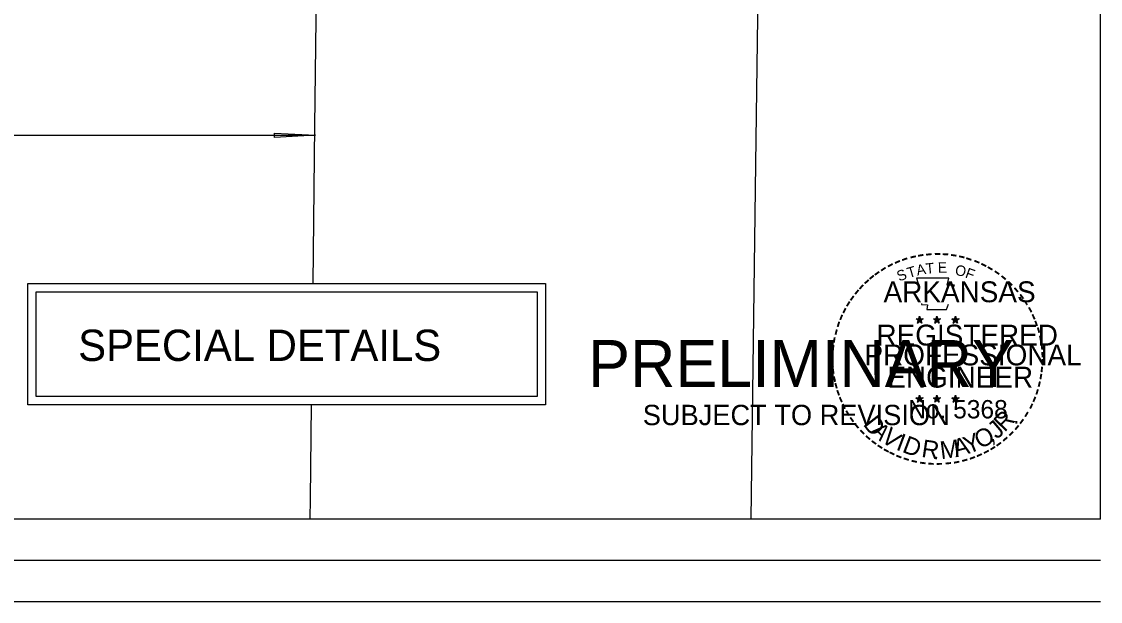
# Model space of a CAD drawing. Extents: x 1944905 to 1956777, y 763871 to 764977.
# Drawn here: x 1949424 to 1949941, y 763871 to 764148 of the extents above; entities that cross this region are included whole.
import ezdxf

# ---------------------------------------------------------------- set-up
doc = ezdxf.new("R2010")
doc.units = 0
for name, color, linetype in [('Default', 7, 'Continuous'), ('R_Border PE', 7, 'Continuous'), ('S_EDGE_PAVEMENT', 7, 'Continuous')]:
    doc.layers.add(name, color=color, linetype=linetype)

msp = doc.modelspace()

# ---------------------------------------------------------------- linework, layer by layer
at = {"layer": 'Default'}
for p, q in [((1949941.01, 763910.07), (1949941.01, 764937.29)), ((1949545.33, 764094.92), (1949545.4, 764094.92)), ((1949545.4, 764094.92), (1949564.95, 764093.95)), ((1949545.4, 764092.97), (1949545.4, 764094.92)), ((1949364.95, 764093.95), (1949564.95, 764093.95)), ((1949564.95, 764093.95), (1949545.4, 764092.97)), ((1949941.01, 763910.07), (1948360.11, 763910.07)), ((1948327.27, 763890.36), (1949941.01, 763890.36)), ((1948327.27, 763870.67), (1949941.01, 763870.67))]:
    msp.add_line(p, q, dxfattribs=at)
for points in [[(1949427.11, 764022.9), (1949675.12, 764022.9), (1949675.12, 763964.87), (1949427.11, 763964.87)], [(1949431.11, 764018.9), (1949671.12, 764018.9), (1949671.12, 763968.87), (1949431.11, 763968.87)]]:
    msp.add_lwpolyline(points, close=True, dxfattribs=at)
at = {"layer": 'R_Border PE'}
for p, q in [((1949854.37, 764007.29), (1949854.12, 764006.09)), ((1949854.37, 764007.29), (1949854.17, 764006.04)), ((1949854.37, 764007.29), (1949854.32, 764006.04)), ((1949854.37, 764005.49), (1949854.37, 764007.29)), ((1949854.37, 764007.29), (1949854.72, 764006.04)), ((1949854.37, 764007.29), (1949854.62, 764006.04)), ((1949854.37, 764007.29), (1949854.52, 764006.09)), ((1949862.72, 764007.29), (1949862.47, 764006.09)), ((1949862.72, 764007.29), (1949862.52, 764006.04)), ((1949862.72, 764007.29), (1949862.67, 764006.04)), ((1949862.72, 764005.49), (1949862.72, 764007.29)), ((1949862.72, 764007.29), (1949863.07, 764006.04)), ((1949862.72, 764007.29), (1949862.97, 764006.04)), ((1949862.72, 764007.29), (1949862.87, 764006.09)), ((1949871.57, 764007.24), (1949871.27, 764006.04)), ((1949871.57, 764007.24), (1949871.37, 764005.99)), ((1949871.57, 764007.24), (1949871.47, 764005.99)), ((1949871.57, 764005.44), (1949871.57, 764007.24)), ((1949871.57, 764007.24), (1949871.92, 764005.99)), ((1949871.57, 764007.24), (1949871.82, 764005.99)), ((1949871.57, 764007.24), (1949871.67, 764006.04)), ((1949852.67, 764006.04), (1949854.37, 764005.49)), ((1949852.67, 764006.04), (1949853.92, 764005.89)), ((1949852.67, 764006.04), (1949853.92, 764005.84)), ((1949852.67, 764006.04), (1949853.87, 764005.74)), ((1949852.67, 764006.04), (1949853.87, 764005.54)), ((1949852.67, 764006.04), (1949853.82, 764005.44)), ((1949852.67, 764006.04), (1949853.82, 764005.34)), ((1949853.32, 764003.99), (1949854.37, 764005.49)), ((1949853.32, 764003.99), (1949853.87, 764005.39)), ((1949853.32, 764003.99), (1949853.92, 764005.24)), ((1949853.32, 764003.99), (1949854.02, 764005.19)), ((1949853.32, 764003.99), (1949854.37, 764005.09)), ((1949853.32, 764003.99), (1949854.17, 764005.04)), ((1949853.32, 764003.99), (1949854.42, 764004.94)), ((1949856.12, 764006.04), (1949854.37, 764005.49)), ((1949855.47, 764003.99), (1949854.37, 764005.49)), ((1949855.47, 764003.99), (1949854.37, 764005.09)), ((1949855.47, 764003.99), (1949854.37, 764004.94)), ((1949855.47, 764003.99), (1949854.57, 764005.04)), ((1949856.12, 764006.04), (1949854.62, 764005.94)), ((1949856.12, 764006.04), (1949854.72, 764005.79)), ((1949856.12, 764006.04), (1949854.72, 764005.69)), ((1949855.47, 764003.99), (1949854.72, 764005.24)), ((1949855.47, 764003.99), (1949854.77, 764005.44)), ((1949855.47, 764003.99), (1949854.87, 764005.44)), ((1949856.12, 764006.04), (1949855.02, 764005.59)), ((1949856.12, 764006.04), (1949855.12, 764005.54)), ((1949856.12, 764006.04), (1949855.17, 764005.49)), ((1949860.97, 764006.04), (1949862.72, 764005.49)), ((1949860.97, 764006.04), (1949862.27, 764005.89)), ((1949860.97, 764006.04), (1949862.27, 764005.84)), ((1949860.97, 764006.04), (1949862.22, 764005.74)), ((1949860.97, 764006.04), (1949862.22, 764005.54)), ((1949860.97, 764006.04), (1949862.17, 764005.44)), ((1949860.97, 764006.04), (1949862.17, 764005.34)), ((1949861.67, 764003.99), (1949862.72, 764005.49)), ((1949861.67, 764003.99), (1949862.22, 764005.39)), ((1949861.67, 764003.99), (1949862.27, 764005.24)), ((1949861.67, 764003.99), (1949862.37, 764005.19)), ((1949861.67, 764003.99), (1949862.72, 764005.09)), ((1949861.67, 764003.99), (1949862.52, 764005.04)), ((1949861.67, 764003.99), (1949862.77, 764004.94)), ((1949864.47, 764006.04), (1949862.72, 764005.49)), ((1949863.82, 764003.99), (1949862.72, 764005.49)), ((1949863.82, 764003.99), (1949862.72, 764005.09)), ((1949863.82, 764003.99), (1949862.72, 764004.94)), ((1949864.47, 764006.04), (1949862.92, 764005.94)), ((1949863.82, 764003.99), (1949862.92, 764005.04)), ((1949864.47, 764006.04), (1949863.02, 764005.79)), ((1949864.47, 764006.04), (1949863.02, 764005.69)), ((1949863.82, 764003.99), (1949863.07, 764005.24)), ((1949863.82, 764003.99), (1949863.12, 764005.44)), ((1949863.82, 764003.99), (1949863.22, 764005.44)), ((1949864.47, 764006.04), (1949863.37, 764005.59)), ((1949864.47, 764006.04), (1949863.47, 764005.54)), ((1949864.47, 764006.04), (1949863.52, 764005.49)), ((1949869.82, 764005.99), (1949871.57, 764005.44)), ((1949869.82, 764005.99), (1949871.12, 764005.84)), ((1949869.82, 764005.99), (1949871.12, 764005.74)), ((1949869.82, 764005.99), (1949871.07, 764005.64)), ((1949869.82, 764005.99), (1949871.02, 764005.49)), ((1949869.82, 764005.99), (1949871.02, 764005.39)), ((1949869.82, 764005.99), (1949871.02, 764005.29)), ((1949870.52, 764003.94), (1949871.57, 764005.44)), ((1949870.52, 764003.94), (1949871.07, 764005.34)), ((1949870.52, 764003.94), (1949871.12, 764005.14)), ((1949870.52, 764003.94), (1949871.22, 764005.14)), ((1949870.52, 764003.94), (1949871.57, 764005.04)), ((1949870.52, 764003.94), (1949871.37, 764004.99)), ((1949870.52, 764003.94), (1949871.62, 764004.89)), ((1949873.32, 764005.99), (1949871.57, 764005.44)), ((1949872.62, 764003.94), (1949871.57, 764005.44)), ((1949872.62, 764003.94), (1949871.57, 764005.04)), ((1949872.62, 764003.94), (1949871.57, 764004.89)), ((1949873.32, 764005.99), (1949871.77, 764005.89)), ((1949872.62, 764003.94), (1949871.77, 764004.99)), ((1949873.32, 764005.99), (1949871.87, 764005.74)), ((1949873.32, 764005.99), (1949871.87, 764005.64)), ((1949872.62, 764003.94), (1949871.92, 764005.19)), ((1949872.62, 764003.94), (1949871.97, 764005.39)), ((1949872.62, 764003.94), (1949872.07, 764005.39)), ((1949873.32, 764005.99), (1949872.22, 764005.54)), ((1949873.32, 764005.99), (1949872.27, 764005.49)), ((1949873.32, 764005.99), (1949872.37, 764005.44)), ((1949852.62, 763968.19), (1949854.37, 763967.64)), ((1949852.62, 763968.19), (1949853.92, 763968.04)), ((1949852.62, 763968.19), (1949853.92, 763967.94)), ((1949852.62, 763968.19), (1949853.87, 763967.84)), ((1949852.62, 763968.19), (1949853.82, 763967.69)), ((1949852.62, 763968.19), (1949853.82, 763967.59)), ((1949852.62, 763968.19), (1949853.82, 763967.44)), ((1949853.32, 763966.14), (1949854.37, 763967.64)), ((1949853.32, 763966.14), (1949853.87, 763967.54)), ((1949853.32, 763966.14), (1949853.92, 763967.34)), ((1949853.32, 763966.14), (1949854.02, 763967.29)), ((1949853.32, 763966.14), (1949854.37, 763967.24)), ((1949853.32, 763966.14), (1949854.17, 763967.19)), ((1949853.32, 763966.14), (1949854.42, 763967.09)), ((1949854.37, 763969.44), (1949854.07, 763968.24)), ((1949854.37, 763969.44), (1949854.17, 763968.19)), ((1949854.37, 763969.44), (1949854.27, 763968.19)), ((1949854.37, 763967.64), (1949854.37, 763969.44)), ((1949854.37, 763969.44), (1949854.72, 763968.19)), ((1949854.37, 763969.44), (1949854.62, 763968.19)), ((1949854.37, 763969.44), (1949854.47, 763968.19)), ((1949856.12, 763968.19), (1949854.37, 763967.64)), ((1949855.42, 763966.14), (1949854.37, 763967.64)), ((1949855.42, 763966.14), (1949854.37, 763967.19)), ((1949855.42, 763966.14), (1949854.37, 763967.09)), ((1949856.12, 763968.19), (1949854.57, 763968.09)), ((1949855.42, 763966.14), (1949854.57, 763967.19)), ((1949856.12, 763968.19), (1949854.67, 763967.94)), ((1949856.12, 763968.19), (1949854.67, 763967.84)), ((1949855.42, 763966.14), (1949854.72, 763967.34)), ((1949855.42, 763966.14), (1949854.77, 763967.59)), ((1949855.42, 763966.14), (1949854.87, 763967.59)), ((1949856.12, 763968.19), (1949855.02, 763967.74)), ((1949856.12, 763968.19), (1949855.07, 763967.69)), ((1949856.12, 763968.19), (1949855.17, 763967.59)), ((1949860.97, 763968.19), (1949862.72, 763967.64)), ((1949860.97, 763968.19), (1949862.27, 763968.04)), ((1949860.97, 763968.19), (1949862.22, 763967.94)), ((1949860.97, 763968.19), (1949862.22, 763967.84)), ((1949860.97, 763968.19), (1949862.17, 763967.69)), ((1949860.97, 763968.19), (1949862.17, 763967.59)), ((1949860.97, 763968.19), (1949862.17, 763967.44)), ((1949861.62, 763966.14), (1949862.72, 763967.64)), ((1949861.62, 763966.14), (1949862.22, 763967.54)), ((1949861.62, 763966.14), (1949862.27, 763967.34)), ((1949861.62, 763966.14), (1949862.37, 763967.29)), ((1949861.62, 763966.14), (1949862.72, 763967.24)), ((1949861.62, 763966.14), (1949862.52, 763967.19)), ((1949861.62, 763966.14), (1949862.72, 763967.09)), ((1949862.72, 763969.44), (1949862.42, 763968.24)), ((1949862.72, 763969.44), (1949862.52, 763968.19)), ((1949862.72, 763969.44), (1949862.62, 763968.19)), ((1949862.72, 763967.64), (1949862.72, 763969.44)), ((1949862.72, 763969.44), (1949863.07, 763968.19)), ((1949862.72, 763969.44), (1949862.97, 763968.19)), ((1949862.72, 763969.44), (1949862.82, 763968.19)), ((1949864.47, 763968.19), (1949862.72, 763967.64)), ((1949863.77, 763966.14), (1949862.72, 763967.64)), ((1949863.77, 763966.14), (1949862.72, 763967.19)), ((1949863.77, 763966.14), (1949862.72, 763967.09)), ((1949864.47, 763968.19), (1949862.92, 763968.09)), ((1949863.77, 763966.14), (1949862.92, 763967.19)), ((1949864.47, 763968.19), (1949863.02, 763967.94)), ((1949864.47, 763968.19), (1949863.02, 763967.84)), ((1949863.77, 763966.14), (1949863.07, 763967.34)), ((1949863.77, 763966.14), (1949863.12, 763967.59)), ((1949863.77, 763966.14), (1949863.22, 763967.59)), ((1949864.47, 763968.19), (1949863.32, 763967.74)), ((1949864.47, 763968.19), (1949863.42, 763967.69)), ((1949864.47, 763968.19), (1949863.52, 763967.59)), ((1949869.82, 763968.14), (1949871.57, 763967.54)), ((1949869.82, 763968.14), (1949871.07, 763967.99)), ((1949869.82, 763968.14), (1949871.07, 763967.89)), ((1949869.82, 763968.14), (1949871.02, 763967.79)), ((1949869.82, 763968.14), (1949871.02, 763967.64)), ((1949869.82, 763968.14), (1949870.97, 763967.49)), ((1949869.82, 763968.14), (1949870.97, 763967.39)), ((1949870.47, 763966.09), (1949871.57, 763967.54)), ((1949870.47, 763966.09), (1949871.02, 763967.44)), ((1949870.47, 763966.09), (1949871.12, 763967.29)), ((1949870.47, 763966.09), (1949871.22, 763967.24)), ((1949870.47, 763966.09), (1949871.37, 763967.14)), ((1949870.47, 763966.09), (1949871.52, 763967.14)), ((1949870.47, 763966.09), (1949871.57, 763967.04)), ((1949871.57, 763969.39), (1949871.27, 763968.14)), ((1949871.57, 763969.39), (1949871.37, 763968.14)), ((1949871.57, 763969.39), (1949871.47, 763968.14)), ((1949872.62, 763966.09), (1949871.52, 763967.14)), ((1949872.62, 763966.09), (1949871.52, 763966.99)), ((1949871.57, 763967.54), (1949871.57, 763969.39)), ((1949871.57, 763969.39), (1949871.87, 763968.14)), ((1949871.57, 763969.39), (1949871.82, 763968.14)), ((1949871.57, 763969.39), (1949871.67, 763968.14)), ((1949873.27, 763968.14), (1949871.57, 763967.54)), ((1949872.62, 763966.09), (1949871.57, 763967.54)), ((1949872.62, 763966.09), (1949871.72, 763967.14)), ((1949873.27, 763968.14), (1949871.77, 763967.99)), ((1949873.27, 763968.14), (1949871.87, 763967.89)), ((1949873.27, 763968.14), (1949871.87, 763967.79)), ((1949872.62, 763966.09), (1949871.92, 763967.54)), ((1949872.62, 763966.09), (1949871.92, 763967.29)), ((1949872.62, 763966.09), (1949872.07, 763967.54)), ((1949873.27, 763968.14), (1949872.17, 763967.64)), ((1949873.27, 763968.14), (1949872.27, 763967.59)), ((1949873.27, 763968.14), (1949872.32, 763967.54))]:
    msp.add_line(p, q, dxfattribs=at)
for points in [[(1949852.87, 764025.44), (1949854.22, 764021.29)], [(1949870.42, 764020.84), (1949871.12, 764022.24), (1949867.67, 764022.14), (1949868.42, 764025.44), (1949852.87, 764025.44)], [(1949855.32, 764013.34), (1949855.32, 764012.89), (1949858.12, 764012.79), (1949857.87, 764010.44), (1949867.22, 764010.44), (1949868.22, 764013.09)], [(1949854.37, 764007.29), (1949855.47, 764003.99), (1949852.67, 764006.04), (1949856.12, 764006.04), (1949853.32, 764003.99), (1949854.37, 764007.29)], [(1949862.72, 764007.29), (1949863.82, 764003.99), (1949860.97, 764006.04), (1949864.47, 764006.04), (1949861.67, 764003.99), (1949862.72, 764007.29)], [(1949871.57, 764007.24), (1949872.62, 764003.94), (1949869.82, 764005.99), (1949873.32, 764005.99), (1949870.52, 764003.94), (1949871.57, 764007.24)], [(1949854.37, 763969.44), (1949855.42, 763966.14), (1949852.62, 763968.19), (1949856.12, 763968.19), (1949853.32, 763966.14), (1949854.37, 763969.44)], [(1949862.72, 763969.44), (1949863.77, 763966.14), (1949860.97, 763968.19), (1949864.47, 763968.19), (1949861.62, 763966.14), (1949862.72, 763969.44)], [(1949871.57, 763969.39), (1949872.62, 763966.09), (1949869.82, 763968.14), (1949873.27, 763968.14), (1949870.47, 763966.09), (1949871.57, 763969.39)]]:
    msp.add_lwpolyline(points, dxfattribs=at)
for centre, radius in [((1949854.37, 764005.49), 0.861), ((1949854.37, 764005.49), 0.78), ((1949854.37, 764005.49), 0.723), ((1949854.37, 764005.49), 0.664), ((1949854.37, 764005.49), 0.579), ((1949854.37, 764005.49), 0.537), ((1949854.37, 764005.49), 0.495), ((1949854.37, 764005.49), 0.426), ((1949854.37, 764005.49), 0.374), ((1949854.37, 764005.49), 0.311), ((1949854.37, 764005.49), 0.248), ((1949854.37, 764005.49), 0.185), ((1949854.37, 764005.49), 0.148), ((1949854.37, 764005.49), 0.0721), ((1949862.72, 764005.49), 0.861), ((1949862.72, 764005.49), 0.78), ((1949862.72, 764005.49), 0.723), ((1949862.72, 764005.49), 0.664), ((1949862.72, 764005.49), 0.579), ((1949862.72, 764005.49), 0.537), ((1949862.72, 764005.49), 0.495), ((1949862.72, 764005.49), 0.426), ((1949862.72, 764005.49), 0.374), ((1949862.72, 764005.49), 0.311), ((1949862.72, 764005.49), 0.248), ((1949862.72, 764005.49), 0.185), ((1949862.72, 764005.49), 0.148), ((1949862.72, 764005.49), 0.0721), ((1949871.56, 764005.43), 0.861), ((1949871.56, 764005.43), 0.78), ((1949871.56, 764005.43), 0.723), ((1949871.56, 764005.43), 0.664), ((1949871.56, 764005.43), 0.579), ((1949871.56, 764005.43), 0.537), ((1949871.56, 764005.43), 0.495), ((1949871.56, 764005.43), 0.426), ((1949871.56, 764005.43), 0.374), ((1949871.56, 764005.43), 0.311), ((1949871.56, 764005.43), 0.248), ((1949871.56, 764005.43), 0.185), ((1949871.56, 764005.43), 0.148), ((1949871.56, 764005.43), 0.0721), ((1949854.35, 763967.63), 0.861), ((1949854.35, 763967.63), 0.78), ((1949854.35, 763967.63), 0.723), ((1949854.35, 763967.63), 0.664), ((1949854.35, 763967.63), 0.579), ((1949854.35, 763967.63), 0.537), ((1949854.35, 763967.63), 0.495), ((1949854.35, 763967.63), 0.426), ((1949854.35, 763967.63), 0.374), ((1949854.35, 763967.63), 0.311), ((1949854.35, 763967.63), 0.248), ((1949854.35, 763967.63), 0.185), ((1949854.35, 763967.63), 0.148), ((1949854.35, 763967.63), 0.0721), ((1949862.7, 763967.63), 0.861), ((1949862.7, 763967.63), 0.78), ((1949862.7, 763967.63), 0.723), ((1949862.7, 763967.63), 0.664), ((1949862.7, 763967.63), 0.579), ((1949862.7, 763967.63), 0.537), ((1949862.7, 763967.63), 0.495), ((1949862.7, 763967.63), 0.426), ((1949862.7, 763967.63), 0.374), ((1949862.7, 763967.63), 0.311), ((1949862.7, 763967.63), 0.248), ((1949862.7, 763967.63), 0.185), ((1949862.7, 763967.63), 0.148), ((1949862.7, 763967.63), 0.0721), ((1949871.54, 763967.57), 0.861), ((1949871.54, 763967.57), 0.78), ((1949871.54, 763967.57), 0.723), ((1949871.54, 763967.57), 0.664), ((1949871.54, 763967.57), 0.579), ((1949871.54, 763967.57), 0.537), ((1949871.54, 763967.57), 0.495), ((1949871.54, 763967.57), 0.426), ((1949871.54, 763967.57), 0.374), ((1949871.54, 763967.57), 0.311), ((1949871.54, 763967.57), 0.248), ((1949871.54, 763967.57), 0.185), ((1949871.54, 763967.57), 0.148), ((1949871.54, 763967.57), 0.0721)]:
    msp.add_circle(centre, radius, dxfattribs=at)
at = {"layer": 'S_EDGE_PAVEMENT'}
for points in [[(1949563.8, 764022.9), (1949564.74, 764098.49), (1949566.96, 764276.97), (1949568.19, 764402.15), (1949569.42, 764527.32), (1949570.65, 764652.49), (1949571.88, 764777.67), (1949573.46, 764887.95)], [(1949773.62, 763910.07), (1949775.95, 764080.27), (1949778.51, 764267.61), (1949779.53, 764399.29), (1949780.54, 764530.97), (1949779.91, 764702.99), (1949781.3, 764840.56), (1949781.63, 764873.29)], [(1949562.4, 763910.07), (1949562.52, 763920.01), (1949563.08, 763964.87)]]:
    msp.add_lwpolyline(points, dxfattribs=at)

# ---------------------------------------------------------------- texts
at = {"layer": 'Default'}
for s, height, p in [('SPECIAL DETAILS', 15, (1949451.29, 763985.86)), ('PRELIMINARY', 22.5, (1949695.6, 763973.37)), ('        SUBJECT TO REVISION', 9.75, (1949692.78, 763955.1))]:
    msp.add_text(s, height=height, dxfattribs=at).set_placement(p)
at = {"layer": 'R_Border PE'}
for s, height, rotation, p in [('-', 8, 28.7918, (1949840.27, 764028.14)), ('-', 8, 24.3072, (1949843.42, 764029.74)), ('-', 8, 19.1761, (1949846.57, 764031.09)), ('-', 8, 13.6301, (1949850.32, 764032.29)), ('-', 8, 10.2193, (1949853.72, 764033.09)), ('T', 5, 6.0228, (1949857.57, 764027.54)), ('-', 8, 5.8968, (1949857.37, 764033.64)), ('-', 8, 0.1862, (1949861.22, 764033.99)), ('E', 5, 0.8323, (1949863.12, 764028.09)), ('-', 8, 357.743, (1949864.87, 764033.94)), ('-', 8, 352.1617, (1949868.57, 764033.64)), ('-', 8, 347.2049, (1949872.17, 764033.09)), ('-', 8, 342.3362, (1949875.32, 764032.29)), ('-', 8, 337.8551, (1949879.02, 764031.19)), ('-', 8, 334.1211, (1949882.17, 764029.84)), ('-', 8, 36.2317, (1949834.37, 764024.29)), ('-', 8, 34.0636, (1949837.27, 764026.29)), ('S', 5, 21.594, (1949844.62, 764023.84)), ('T', 5, 16.4036, (1949849.22, 764025.49)), ('A', 5, 11.2132, (1949853.32, 764026.74)), ('O', 5, 350.4515, (1949871.12, 764027.04)), ('F', 5, 340.0707, (1949875.87, 764025.94)), ('-', 8, 329.6409, (1949885.07, 764028.44)), ('-', 8, 325.8627, (1949888.27, 764026.59)), ('-', 8, 48.4231, (1949827.62, 764017.94)), ('-', 8, 42.9622, (1949829.82, 764020.34)), ('-', 8, 38.9507, (1949832.02, 764022.44)), ('-', 8, 320.5297, (1949891.32, 764024.49)), ('-', 8, 315.5786, (1949894.32, 764022.04)), ('-', 8, 54.2325, (1949823.52, 764012.69)), ('-', 8, 50.6142, (1949825.57, 764015.54)), ('-', 8, 309.8797, (1949897.17, 764019.29)), ('-', 8, 306.6522, (1949899.82, 764016.29)), ('-', 8, 58.0706, (1949821.87, 764010.04)), ('-', 7, 303.6753, (1949902.22, 764013.44)), ('-', 8, 67.7743, (1949819.02, 764003.94)), ('-', 8, 62.8713, (1949820.32, 764006.99)), ('-', 8, 299.6684, (1949903.82, 764010.39)), ('-', 8, 294.6628, (1949905.42, 764007.34)), ('-', 8, 72.3945, (1949817.92, 764000.79)), ('-', 8, 290.5728, (1949906.72, 764004.44)), ('-', 8, 285.1233, (1949907.92, 764001.54)), ('-', 8, 81.2013, (1949816.27, 763993.64)), ('-', 8, 75.461, (1949816.97, 763997.19)), ('-', 8, 280.5493, (1949908.92, 763997.84)), ('-', 8, 85.1863, (1949815.92, 763990.19)), ('-', 8, 276.5962, (1949909.72, 763993.99)), ('-', 8, 89.0622, (1949815.77, 763986.69)), ('-', 8, 274.3301, (1949910.02, 763990.39)), ('-', 8, 269.9407, (1949910.17, 763987.24)), ('-', 8, 94.1959, (1949815.97, 763983.04)), ('-', 8, 98.9479, (1949816.32, 763979.74)), ('-', 8, 263.5172, (1949910.07, 763983.89)), ('-', 8, 101.7149, (1949817.02, 763976.04)), ('-', 8, 255.7626, (1949909.17, 763977.24)), ('-', 8, 260.9953, (1949909.72, 763980.64)), ('-', 8, 105.4578, (1949817.82, 763973.09)), ('-', 8, 109.0874, (1949818.87, 763969.94)), ('-', 8, 252.8681, (1949908.27, 763973.64)), ('-', 8, 114.0643, (1949820.17, 763966.94)), ('-', 8, 115.7289, (1949821.67, 763963.84)), ('-', 8, 244.6197, (1949905.87, 763967.14)), ('-', 8, 247.8887, (1949907.17, 763970.29)), ('-', 8, 120.4471, (1949823.47, 763960.94)), ('R', 8.47, 46.2922, (1949895.12, 763951.44)), ('-', 8, 239.0712, (1949903.87, 763963.39)), ('-', 8, 125.8934, (1949825.47, 763958.14)), ('-', 8, 130.7181, (1949827.77, 763955.34)), ('D', 8.47, 308.0267, (1949827.02, 763955.44)), ('A', 7.7, 314.1683, (1949830.77, 763951.99)), ('J', 8.47, 40.1506, (1949891.37, 763948.09)), ('-', 8, 231.2538, (1949899.72, 763957.29)), ('-', 8, 233.8452, (1949901.87, 763960.14)), ('-', 8, 134.2238, (1949830.37, 763952.64)), ('-', 8, 138.9338, (1949833.02, 763950.29)), ('V', 8.47, 322.0751, (1949835.42, 763947.94)), ('ID', 8.47, 339.2447, (1949842.67, 763943.49)), ('Y', 8.47, 21.7259, (1949877.47, 763941.09)), ('O', 8.47, 27.8675, (1949883.37, 763943.49)), ('-', 8, 225.7653, (1949897.32, 763954.49)), ('-', 8, 144.6463, (1949835.77, 763948.29)), ('-', 8, 148.0898, (1949838.57, 763946.44)), ('R', 8.47, 351.4846, (1949854.97, 763939.94)), ('M', 8.47, 7.3842, (1949864.67, 763938.79)), ('A', 8.47, 15.0444, (1949871.67, 763939.74)), ('-', 8, 212.2491, (1949889.32, 763947.64)), (',', 8.45, 13.6684, (1949888.22, 763946.74)), ('-', 8, 215.7363, (1949891.97, 763949.54)), ('-', 8, 221.0851, (1949894.72, 763951.94)), ('-', 8, 151.5704, (1949841.47, 763944.79)), ('-', 8, 154.6002, (1949844.07, 763943.59)), ('-', 8, 158.5612, (1949847.22, 763942.29)), ('-', 8, 162.7983, (1949850.62, 763941.24)), ('.', 7.7, 351.0179, (1949860.77, 763938.99)), ('-', 8, 200.7184, (1949880.27, 763942.94)), ('-', 8, 204.2516, (1949883.37, 763944.29)), ('-', 8, 207.3568, (1949886.52, 763945.89)), ('-', 8, 167.5555, (1949854.22, 763940.39)), ('-', 8, 173.1155, (1949858.07, 763939.84)), ('-', 8, 176.5183, (1949861.82, 763939.59)), ('-', 8, 181.5918, (1949865.52, 763939.69)), ('-', 8, 185.8167, (1949869.57, 763940.09)), ('-', 8, 191.2858, (1949873.27, 763940.74)), ('-', 8, 195.4743, (1949876.92, 763941.74))]:
    msp.add_text(s, height=height, rotation=rotation, dxfattribs=at).set_placement(p)
for s, height, p in [('ARKANSAS', 10, (1949837.12, 764013.99)), ('REGISTERED', 10, (1949833.72, 763993.24)), ('PROFESSIONAL', 9.9999, (1949827.97, 763983.74)), ('ENGINEER', 10, (1949838.92, 763973.09)), ('No. 5368', 8.785, (1949848.92, 763958.34)), ('.', 8.45, (1949899.17, 763955.84))]:
    msp.add_text(s, height=height, dxfattribs=at).set_placement(p)

doc.saveas('drawing.dxf')
